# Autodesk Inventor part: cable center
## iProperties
Author: Administrator
Shininess: 20.0
PropertySet Name: _Private Model Information
Created: 2001-03
Part Number: cable center
Document SubType Name: Modeling
Designer: Administrator
Control State: 0
Master: False
Checked Out: False
PropertySet Name: Design Tracking Control
Density: 0.0
Volumn: 0.0
Area: 0.0
PropertySet Name: Model Information
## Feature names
1. Extrusion1
